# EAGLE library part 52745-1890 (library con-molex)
FFC/FPC-to-Board 0.50mm (.020") SMT Top Contact Right Angle, ZIF, Style Receptacle 52745 / 52435 Source: http://www.molex.com/product/ffc/52745.html
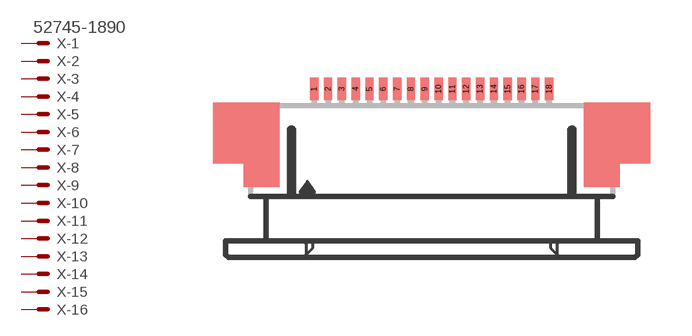
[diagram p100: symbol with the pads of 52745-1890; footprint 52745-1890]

Designator prefix X; gates -1=MV -2=M -3=M -4=M -5=M -6=M -7=M -8=M -9=M -10=M -11=M -12=M -13=M -14=M -15=M -16=M -17=M -18=M

## 52745-1890 (MPN: 52745-1890; OC_FARNELL: unknown; OC_NEWARK: 66F4273)  [52745-1890]
1  -1:S  pas
2  -2:S  pas
3  -3:S  pas
4  -4:S  pas
5  -5:S  pas
6  -6:S  pas
7  -7:S  pas
8  -8:S  pas
9  -9:S  pas
10  -10:S  pas
11  -11:S  pas
12  -12:S  pas
13  -13:S  pas
14  -14:S  pas
15  -15:S  pas
16  -16:S  pas
17  -17:S  pas
18  -18:S  pas

## Footprint 52745-1890 (pad centres in mm)
FFC/FPC-to-Board 0.50mm (.020") SMT Top Contact Right Angle, ZIF, Style Receptacle 52745 / 52435 Source: http://www.molex.com/product/ffc/52745.html
smd 0.3 x 0.8: 1 -4.25,2.5; 2 -3.75,2.5; 3 -3.25,2.5; 4 -2.75,2.5; 5 -2.25,2.5; 6 -1.75,2.5; 7 -1.25,2.5; 8 -0.75,2.5; 9 -0.25,2.5; 10 0.25,2.5; 11 0.75,2.5; 12 1.25,2.5; 13 1.75,2.5; 14 2.25,2.5; 15 2.75,2.5; 16 3.25,2.5; 17 3.75,2.5; 18 4.25,2.5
